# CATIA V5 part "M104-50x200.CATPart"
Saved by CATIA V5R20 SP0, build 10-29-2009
Part number: M104-50x200
Source: Unknown
Bounding box of the stored display mesh (mm): x -24.865 to 24.865, y -24.997 to 24.997, z 0 to 200
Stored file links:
  C:\Users\Utente\Desktop\IO LAVORO\3D X SITO CF\X SITO\M104\M104-50x200.CATPart
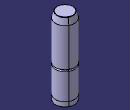
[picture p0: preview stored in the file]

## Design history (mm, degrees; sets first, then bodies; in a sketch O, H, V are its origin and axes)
Body1 (main body)
  Solid1 "PartBody": solid without history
